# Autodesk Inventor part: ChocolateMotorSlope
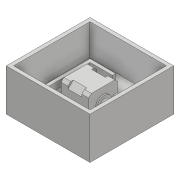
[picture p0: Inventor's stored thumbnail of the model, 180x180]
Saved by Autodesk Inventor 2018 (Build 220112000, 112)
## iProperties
Created: 2018-03
Part Number: ChocolateMotorSlope
Material: Generic
Document SubType Name: Modeling
Designer: arivu
Density: 1 g/cm^3
Appearance: Default
Author: arivu
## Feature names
1. Split1
2. Extrusion1
3. Split2
4. Extrusion2
5. Shell1
6. Extrusion3
7. Shell2
8. Sweep1
9. Extrusion5
10. Extrusion6
11. Extrusion7
12. Extrusion8
13. Extrusion9
14. Extrusion10
15. Extrusion11
16. Extrusion12
17. Extrusion13
18. Split3
19. Split4
20. Extrusion14
21. Extrusion16
22. Sweep3
23. Sweep4
24. Sweep5
25. Sweep6
26. Sweep7
27. Extrusion17
28. TaggingFeature1
## Parameters: d0 = 3 mm, d1 = 0, d2 = 4 mm, d4 = 0, d14 = 9 mm, d15 = 0, d16 = 2 mm, d17 = 5 mm, d21 = 13.3 mm, d22 = 0, d23 = 2 mm, d24 = 1 mm, d26 = 15 mm, d27 = 135 deg, d28 = 0, d29 = 0, d30 = 0, d31 = 0, d48 = 0, d49 = 0, d50 = 90 deg, d51 = 2 mm, d52 = 0, d53 = 2 mm, d54 = 0, d55 = 2 mm, d56 = 0, d57 = 2 mm, d58 = 0, d59 = 12 deg, d60 = 2 mm, d61 = 0, d62 = 12 deg, d63 = 2 mm, d64 = 0, d65 = 12 deg, d66 = 2 mm, d67 = 0, d68 = 168 deg, d70 = -4 mm, d71 = 12 deg, d72 = 2 mm, d73 = 0, d74 = 2 mm, d75 = 0, d81 = 3.5 mm, d82 = 3.5 mm, d83 = 13 mm, d89 = 0, d90 = 0, d91 = 0, d92 = 0, d93 = 0, d94 = 0, d95 = 0, d96 = 0, d97 = 0, d98 = 0, d99 = 5 mm, d100 = 0, d101 = 4 mm, d102 = 4 mm, d105 = 4 mm, d126 = 3.5 mm, d127 = 3 mm, d128 = 0, d130 = 3.3 mm, d131 = 3.3 mm, d132 = 3.3 mm, d133 = 3.3 mm, d134 = 3.3 mm, d135 = 3.3 mm, d136 = 3 mm, d137 = 0
